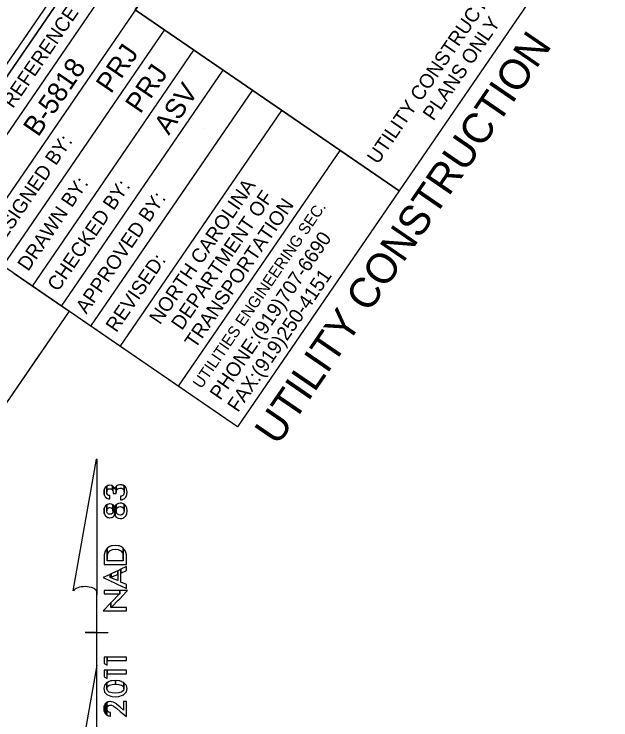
# Model space of a CAD drawing. Extents: x 1439200 to 1641636, y 393269 to 606444.
# Drawn here: x 1641246 to 1641330.1, y 393923.4 to 394022.9 of the extents above; entities that cross this region are included whole.
import ezdxf

# ---------------------------------------------------------------- set-up
doc = ezdxf.new("R2010")
doc.units = 0
for name, color, linetype in [('North Arrow NAD83 CELL', 7, 'Continuous'), ('Sheet Data Field CELL', 7, 'Continuous'), ('Sheet Plot Border Inside CELL', 7, 'Continuous'), ('Sheet Sticker Exception Certification CELL', 7, 'Continuous'), ('UC Plan Sheet 34 CELL', 7, 'Continuous')]:
    doc.layers.add(name, color=color, linetype=linetype)

msp = doc.modelspace()

# ---------------------------------------------------------------- linework, layer by layer
at = {"layer": 'North Arrow NAD83 CELL'}
for p, q in [((1641275.714, 393965.954), (1641254.905, 393980.224)), ((1641251.013, 393977.029), (1641216.651, 393926.919)), ((1641249.54, 393974.88), (1641224.439, 393938.276)), ((1641254.348, 393941.624), (1641257.636, 393960.163)), ((1641257.656, 393960.163), (1641257.636, 393960.163)), ((1641257.656, 393960.163), (1641257.636, 393960.163)), ((1641257.656, 393960.163), (1641257.648, 393941.043)), ((1641257.644, 393931.123), (1641257.648, 393941.603)), ((1641257.648, 393941.043), (1641257.648, 393941.583)), ((1641256.046, 393935.764), (1641256.026, 393935.764)), ((1641257.466, 393935.763), (1641256.046, 393935.764)), ((1641256.066, 393935.764), (1641259.266, 393935.762)), ((1641257.644, 393931.123), (1641254.296, 393912.224)), ((1641257.656, 393912.303), (1641257.644, 393931.123))]:
    msp.add_line(p, q, dxfattribs=at)
for points in [[(1641259.444, 393954.569), (1641259.483, 393954.565), (1641259.483, 393955.036), (1641259.444, 393955.038), (1641259.329, 393955.065), (1641259.313, 393955.07), (1641259.311, 393955.07), (1641259.175, 393955.166), (1641259.168, 393955.177), (1641259.158, 393955.195), (1641259.091, 393955.313), (1641259.077, 393955.397), (1641259.072, 393955.42), (1641259.057, 393955.51), (1641259.057, 393956.376), (1641258.884, 393956.258), (1641258.836, 393956.176), (1641258.836, 393956.175), (1641258.697, 393955.935), (1641258.684, 393955.843), (1641258.684, 393955.182), (1641258.698, 393955.155), (1641258.837, 393954.872), (1641258.884, 393954.832), (1641259.057, 393954.686), (1641259.073, 393954.673), (1641259.077, 393954.672), (1641259.091, 393954.666), (1641259.158, 393954.642), (1641259.169, 393954.638), (1641259.175, 393954.636), (1641259.311, 393954.587), (1641259.313, 393954.586), (1641259.329, 393954.581)], [(1641259.804, 393955.9), (1641259.859, 393955.859), (1641259.859, 393956.406), (1641259.804, 393956.442), (1641259.699, 393956.461), (1641259.502, 393956.498), (1641259.487, 393956.501), (1641259.482, 393956.5), (1641259.443, 393956.494), (1641259.329, 393956.474), (1641259.312, 393956.471), (1641259.31, 393956.471), (1641259.31, 393956.471), (1641259.174, 393956.448), (1641259.168, 393956.447), (1641259.158, 393956.445), (1641259.091, 393956.4), (1641259.076, 393956.389), (1641259.072, 393956.387), (1641259.057, 393956.376), (1641259.057, 393955.51), (1641259.072, 393955.661), (1641259.076, 393955.702), (1641259.091, 393955.728), (1641259.158, 393955.853), (1641259.168, 393955.873), (1641259.174, 393955.877), (1641259.31, 393955.974), (1641259.312, 393955.976), (1641259.329, 393955.979), (1641259.443, 393956.001), (1641259.482, 393956.008), (1641259.487, 393956.009), (1641259.502, 393956.012), (1641259.7, 393955.977)], [(1641259.859, 393955.858), (1641259.941, 393955.693), (1641259.941, 393956.355), (1641259.859, 393956.406)], [(1641260.255, 393955.353), (1641260.382, 393955.353), (1641260.382, 393956.324), (1641260.255, 393956.155), (1641260.195, 393955.95), (1641260.155, 393956.101), (1641260.035, 393956.295), (1641259.965, 393956.339), (1641259.964, 393956.34), (1641259.941, 393956.355), (1641259.941, 393955.692), (1641259.965, 393955.5), (1641259.966, 393955.353), (1641260.036, 393955.353), (1641260.155, 393955.353), (1641260.195, 393955.353)], [(1641261.479, 393955.716), (1641261.514, 393955.544), (1641261.514, 393956.405), (1641261.479, 393956.427), (1641261.464, 393956.437), (1641261.464, 393956.437), (1641261.354, 393956.509), (1641261.337, 393956.512), (1641261.33, 393956.513), (1641261.253, 393956.528), (1641261.149, 393956.547), (1641261.138, 393956.549), (1641261.018, 393956.571), (1641260.921, 393956.558), (1641260.719, 393956.53), (1641260.693, 393956.527), (1641260.55, 393956.451), (1641260.435, 393956.39), (1641260.429, 393956.387), (1641260.388, 393956.332), (1641260.382, 393956.324), (1641260.382, 393955.455), (1641260.388, 393955.607), (1641260.429, 393955.775), (1641260.435, 393955.8), (1641260.551, 393955.959), (1641260.693, 393956.043), (1641260.72, 393956.059), (1641260.922, 393956.094), (1641261.018, 393956.084), (1641261.138, 393956.072), (1641261.149, 393956.066), (1641261.253, 393956.014), (1641261.331, 393955.975), (1641261.337, 393955.966), (1641261.354, 393955.941), (1641261.465, 393955.788)], [(1641261.905, 393955.153), (1641261.939, 393955.555), (1641261.905, 393955.74), (1641261.86, 393955.981), (1641261.749, 393956.164), (1641261.661, 393956.308), (1641261.519, 393956.401), (1641261.514, 393956.405), (1641261.514, 393955.544), (1641261.479, 393955.251), (1641261.465, 393955.23), (1641261.355, 393955.068), (1641261.337, 393955.042), (1641261.331, 393955.038), (1641261.254, 393954.998), (1641261.15, 393954.943), (1641261.138, 393954.942), (1641261.019, 393954.934), (1641261.008, 393954.934), (1641261.008, 393954.437), (1641261.019, 393954.439), (1641261.139, 393954.456), (1641261.15, 393954.457), (1641261.254, 393954.472), (1641261.331, 393954.504), (1641261.337, 393954.507), (1641261.355, 393954.515), (1641261.465, 393954.56), (1641261.48, 393954.567), (1641261.515, 393954.581), (1641261.52, 393954.584), (1641261.662, 393954.73), (1641261.749, 393954.82), (1641261.861, 393955.058)], [(1641258.642, 393955.552), (1641258.684, 393955.182), (1641258.684, 393955.843)], [(1641258.693, 393952.537), (1641258.699, 393952.501), (1641258.698, 393953.277), (1641258.693, 393953.268), (1641258.643, 393952.886), (1641258.643, 393952.885)], [(1641260.093, 393952.207), (1641260.176, 393952.361), (1641260.176, 393953.414), (1641260.092, 393953.578), (1641260.088, 393953.582), (1641259.962, 393953.72), (1641259.96, 393953.723), (1641259.931, 393953.738), (1641259.932, 393952.883), (1641259.905, 393952.685), (1641259.814, 393952.532), (1641259.747, 393952.487), (1641259.747, 393952.487), (1641259.744, 393952.485), (1641259.674, 393952.439), (1641259.502, 393952.407), (1641259.44, 393952.418), (1641259.321, 393952.439), (1641259.173, 393952.549), (1641259.17, 393952.552), (1641259.124, 393952.636), (1641259.087, 393952.703), (1641259.062, 393952.891), (1641259.062, 393953.738), (1641258.869, 393953.592), (1641258.698, 393953.277), (1641258.699, 393952.501), (1641258.87, 393952.177), (1641259.063, 393952.032), (1641259.087, 393952.013), (1641259.124, 393951.985), (1641259.171, 393951.973), (1641259.173, 393951.972), (1641259.321, 393951.934), (1641259.441, 393951.903), (1641259.503, 393951.91), (1641259.675, 393951.93), (1641259.745, 393951.939), (1641259.748, 393951.941), (1641259.815, 393951.974), (1641259.905, 393952.02), (1641259.932, 393952.034), (1641259.961, 393952.048), (1641259.963, 393952.05), (1641260.089, 393952.2)], [(1641259.905, 393953.089), (1641259.932, 393952.883), (1641259.931, 393953.738), (1641259.905, 393953.753), (1641259.814, 393953.801), (1641259.747, 393953.838), (1641259.744, 393953.838), (1641259.674, 393953.845), (1641259.502, 393953.863), (1641259.502, 393953.862), (1641259.44, 393953.869), (1641259.32, 393953.837), (1641259.172, 393953.798), (1641259.17, 393953.797), (1641259.124, 393953.785), (1641259.087, 393953.757), (1641259.062, 393953.738), (1641259.062, 393952.891), (1641259.087, 393953.069), (1641259.124, 393953.14), (1641259.17, 393953.229), (1641259.172, 393953.23), (1641259.321, 393953.335), (1641259.44, 393953.356), (1641259.502, 393953.367), (1641259.674, 393953.335), (1641259.744, 393953.288), (1641259.747, 393953.286), (1641259.814, 393953.242)], [(1641260.245, 393952.202), (1641260.25, 393952.191), (1641260.25, 393953.579), (1641260.245, 393953.573), (1641260.176, 393953.414), (1641260.176, 393952.36)], [(1641261.894, 393952.49), (1641261.94, 393952.887), (1641261.893, 393953.291), (1641261.892, 393953.293), (1641261.728, 393953.646), (1641261.726, 393953.648), (1641261.519, 393953.813), (1641261.519, 393952.886), (1641261.487, 393952.638), (1641261.432, 393952.548), (1641261.432, 393952.547), (1641261.371, 393952.447), (1641261.19, 393952.332), (1641261.077, 393952.311), (1641261.074, 393952.31), (1641260.97, 393952.291), (1641260.738, 393952.332), (1641260.713, 393952.35), (1641260.547, 393952.468), (1641260.546, 393952.47), (1641260.438, 393952.664), (1641260.425, 393952.762), (1641260.418, 393952.819), (1641260.41, 393952.885), (1641260.409, 393953.769), (1641260.25, 393953.58), (1641260.25, 393952.19), (1641260.41, 393952.001), (1641260.418, 393951.991), (1641260.426, 393951.983), (1641260.438, 393951.976), (1641260.546, 393951.921), (1641260.547, 393951.921), (1641260.713, 393951.838), (1641260.738, 393951.835), (1641260.97, 393951.807), (1641261.074, 393951.794), (1641261.077, 393951.794), (1641261.19, 393951.824), (1641261.371, 393951.873), (1641261.432, 393951.889), (1641261.487, 393951.933), (1641261.52, 393951.96), (1641261.727, 393952.127), (1641261.729, 393952.131), (1641261.893, 393952.481)], [(1641261.486, 393953.134), (1641261.519, 393952.886), (1641261.519, 393953.813), (1641261.486, 393953.839), (1641261.431, 393953.883), (1641261.371, 393953.899), (1641261.189, 393953.947), (1641261.076, 393953.977), (1641261.073, 393953.978), (1641260.969, 393953.966), (1641260.969, 393953.965), (1641260.737, 393953.939), (1641260.712, 393953.936), (1641260.546, 393953.848), (1641260.545, 393953.847), (1641260.437, 393953.79), (1641260.425, 393953.783), (1641260.418, 393953.78), (1641260.409, 393953.77), (1641260.41, 393952.885), (1641260.418, 393952.951), (1641260.425, 393953.009), (1641260.438, 393953.108), (1641260.546, 393953.306), (1641260.547, 393953.306), (1641260.712, 393953.424), (1641260.737, 393953.442), (1641260.969, 393953.481), (1641261.073, 393953.463), (1641261.076, 393953.462), (1641261.19, 393953.442), (1641261.371, 393953.325), (1641261.432, 393953.224)], [(1641261.848, 393945.328), (1641261.861, 393945.328), (1641261.86, 393946.025), (1641261.848, 393946.687), (1641261.708, 393947.229), (1641261.393, 393947.636), (1641261.394, 393945.843), (1641261.383, 393945.843), (1641261.365, 393945.843), (1641261.285, 393945.842), (1641261.042, 393945.842), (1641260.857, 393945.842), (1641260.683, 393945.842), (1641260.271, 393945.842), (1641260.268, 393945.842), (1641259.853, 393945.842), (1641259.684, 393945.842), (1641259.494, 393945.842), (1641259.251, 393945.842), (1641259.176, 393945.842), (1641259.153, 393945.842), (1641259.14, 393945.842), (1641259.14, 393947.626), (1641258.832, 393947.228), (1641258.693, 393946.685), (1641258.677, 393946.024), (1641258.677, 393945.326), (1641258.693, 393945.326), (1641258.832, 393945.326), (1641259.141, 393945.326), (1641259.153, 393945.326), (1641259.177, 393945.326), (1641259.251, 393945.326), (1641259.494, 393945.327), (1641259.685, 393945.327), (1641259.853, 393945.327), (1641260.269, 393945.327), (1641260.271, 393945.327), (1641260.683, 393945.327), (1641260.857, 393945.327), (1641261.042, 393945.327), (1641261.286, 393945.327), (1641261.365, 393945.327), (1641261.384, 393945.327), (1641261.394, 393945.327), (1641261.709, 393945.328)], [(1641261.364, 393946.693), (1641261.383, 393946.627), (1641261.383, 393947.649), (1641261.364, 393947.673), (1641261.285, 393947.716), (1641261.041, 393947.846), (1641260.856, 393947.945), (1641260.682, 393947.969), (1641260.682, 393947.969), (1641260.27, 393948.026), (1641260.268, 393948.026), (1641259.852, 393947.968), (1641259.683, 393947.945), (1641259.493, 393947.842), (1641259.25, 393947.712), (1641259.176, 393947.672), (1641259.152, 393947.642), (1641259.14, 393947.626), (1641259.14, 393946.03), (1641259.152, 393946.626), (1641259.176, 393946.71), (1641259.25, 393946.976), (1641259.493, 393947.263), (1641259.684, 393947.356), (1641259.853, 393947.439), (1641260.268, 393947.491), (1641260.27, 393947.49), (1641260.682, 393947.439), (1641260.856, 393947.354), (1641261.042, 393947.263), (1641261.285, 393946.977)], [(1641261.383, 393946.626), (1641261.394, 393946.031), (1641261.393, 393947.636), (1641261.383, 393947.649)], [(1641261.042, 393942.33), (1641261.862, 393941.948), (1641261.862, 393942.492), (1641261.041, 393942.86), (1641261.041, 393944.646), (1641260.609, 393944.445), (1641260.61, 393943.052), (1641259.885, 393943.377), (1641259.883, 393943.378), (1641259.702, 393943.444), (1641259.697, 393943.445), (1641259.523, 393943.494), (1641259.522, 393943.938), (1641258.554, 393943.487), (1641259.523, 393943.036), (1641259.697, 393942.955), (1641259.702, 393942.953), (1641259.883, 393942.868), (1641259.885, 393942.867), (1641260.61, 393942.53)], [(1641259.885, 393943.615), (1641260.609, 393943.936), (1641260.609, 393944.445), (1641259.885, 393944.107), (1641259.883, 393944.106), (1641259.702, 393944.022), (1641259.696, 393944.02), (1641259.697, 393943.545), (1641259.702, 393943.547), (1641259.883, 393943.614)], [(1641261.041, 393944.12), (1641261.861, 393944.483), (1641261.861, 393945.029), (1641261.041, 393944.646)], [(1641259.523, 393943.493), (1641259.697, 393943.545), (1641259.696, 393944.019), (1641259.522, 393943.938)], [(1641260.678, 393941.173), (1641260.886, 393941.173), (1641260.885, 393941.648), (1641260.678, 393941.648), (1641260.501, 393941.648), (1641260.004, 393941.648), (1641259.814, 393941.647), (1641258.678, 393941.647), (1641258.679, 393941.172), (1641259.814, 393941.173), (1641260.005, 393941.173), (1641260.501, 393941.173)], [(1641261.863, 393941.521), (1641261.986, 393941.648), (1641261.863, 393941.648), (1641260.885, 393941.648), (1641260.886, 393941.173), (1641260.679, 393940.998), (1641260.501, 393940.825), (1641260.005, 393940.309), (1641259.814, 393940.111), (1641259.653, 393939.943), (1641259.653, 393939.279), (1641259.815, 393939.406), (1641260.005, 393939.586), (1641260.502, 393940.103), (1641260.679, 393940.287), (1641260.886, 393940.503)], [(1641260.887, 393938.805), (1641261.864, 393938.806), (1641261.864, 393939.28), (1641260.886, 393939.279), (1641260.679, 393939.279), (1641260.502, 393939.279), (1641260.005, 393939.279), (1641259.815, 393939.279), (1641259.653, 393939.279), (1641259.653, 393939.943), (1641258.556, 393938.804), (1641259.653, 393938.805), (1641259.815, 393938.805), (1641260.006, 393938.805), (1641260.502, 393938.805), (1641260.679, 393938.805)], [(1641258.694, 393931.361), (1641259.107, 393931.159), (1641259.106, 393932.289), (1641258.693, 393932.289)], [(1641259.107, 393931.815), (1641261.846, 393931.816), (1641261.846, 393932.29), (1641259.106, 393932.289)], [(1641258.694, 393929.486), (1641259.108, 393929.284), (1641259.107, 393930.414), (1641258.694, 393930.414)], [(1641259.107, 393929.94), (1641261.847, 393929.941), (1641261.847, 393930.415), (1641259.107, 393930.414)], [(1641261.838, 393927.38), (1641261.93, 393927.832), (1641261.837, 393928.273), (1641261.832, 393928.298), (1641261.488, 393928.673), (1641261.488, 393927.825), (1641261.482, 393927.803), (1641261.479, 393927.792), (1641261.412, 393927.555), (1641261.156, 393927.357), (1641261.154, 393927.357), (1641261.154, 393927.356), (1641260.925, 393927.294), (1641260.921, 393927.293), (1641260.756, 393927.247), (1641260.746, 393927.245), (1641260.287, 393927.204), (1641260.282, 393927.204), (1641260.277, 393927.205), (1641259.819, 393927.244), (1641259.645, 393927.291), (1641259.64, 393927.292), (1641259.418, 393927.352), (1641259.41, 393927.354), (1641259.152, 393927.554), (1641259.085, 393927.81), (1641259.082, 393927.818), (1641259.076, 393927.841), (1641259.076, 393928.68), (1641258.737, 393928.31), (1641258.733, 393928.291), (1641258.633, 393927.836), (1641258.633, 393927.836), (1641258.733, 393927.364), (1641258.738, 393927.36), (1641259.077, 393926.994), (1641259.083, 393926.987), (1641259.085, 393926.985), (1641259.152, 393926.957), (1641259.411, 393926.851), (1641259.418, 393926.848), (1641259.64, 393926.757), (1641259.645, 393926.756), (1641259.82, 393926.738), (1641260.277, 393926.69), (1641260.282, 393926.689), (1641260.287, 393926.69), (1641260.746, 393926.736), (1641260.756, 393926.737), (1641260.921, 393926.754), (1641260.925, 393926.754), (1641261.154, 393926.848), (1641261.156, 393926.849), (1641261.412, 393926.953), (1641261.479, 393926.981), (1641261.482, 393926.982), (1641261.489, 393926.989), (1641261.833, 393927.374)], [(1641259.819, 393928.424), (1641260.276, 393928.461), (1641260.276, 393928.976), (1641259.819, 393928.931), (1641259.645, 393928.914), (1641259.639, 393928.912), (1641259.639, 393928.912), (1641259.417, 393928.822), (1641259.417, 393928.822), (1641259.41, 393928.819), (1641259.151, 393928.715), (1641259.151, 393928.715), (1641259.084, 393928.688), (1641259.082, 393928.687), (1641259.076, 393928.68), (1641259.076, 393927.841), (1641259.082, 393927.864), (1641259.085, 393927.871), (1641259.151, 393928.112), (1641259.41, 393928.311), (1641259.417, 393928.317), (1641259.64, 393928.376), (1641259.645, 393928.377)], [(1641261.482, 393927.848), (1641261.488, 393927.825), (1641261.488, 393928.673), (1641261.482, 393928.68), (1641261.479, 393928.683), (1641261.412, 393928.71), (1641261.155, 393928.816), (1641261.153, 393928.817), (1641260.924, 393928.912), (1641260.92, 393928.914), (1641260.755, 393928.93), (1641260.745, 393928.931), (1641260.286, 393928.976), (1641260.281, 393928.976), (1641260.276, 393928.976), (1641260.276, 393928.461), (1641260.281, 393928.461), (1641260.287, 393928.46), (1641260.745, 393928.424), (1641260.755, 393928.423), (1641260.92, 393928.378), (1641260.924, 393928.377), (1641261.153, 393928.316), (1641261.155, 393928.314), (1641261.412, 393928.113), (1641261.479, 393927.86)], [(1641258.823, 393924.343), (1641258.828, 393924.333), (1641258.828, 393925.693), (1641258.823, 393925.689), (1641258.688, 393925.39), (1641258.671, 393925.354), (1641258.634, 393924.982), (1641258.634, 393924.982), (1641258.672, 393924.735), (1641258.688, 393924.626)], [(1641258.828, 393924.333), (1641259.063, 393924.112), (1641259.063, 393925.897), (1641258.828, 393925.693)], [(1641259.517, 393923.974), (1641259.573, 393923.97), (1641259.573, 393924.467), (1641259.517, 393924.472), (1641259.492, 393924.475), (1641259.486, 393924.477), (1641259.348, 393924.527), (1641259.334, 393924.537), (1641259.309, 393924.556), (1641259.194, 393924.645), (1641259.163, 393924.707), (1641259.104, 393924.825), (1641259.098, 393924.838), (1641259.089, 393925.084), (1641259.088, 393925.919), (1641259.063, 393925.897), (1641259.063, 393924.111), (1641259.089, 393924.1), (1641259.098, 393924.096), (1641259.105, 393924.093), (1641259.163, 393924.067), (1641259.194, 393924.054), (1641259.31, 393924.002), (1641259.334, 393923.991), (1641259.348, 393923.99), (1641259.486, 393923.977), (1641259.492, 393923.977)], [(1641261.437, 393924.237), (1641261.849, 393923.893), (1641261.849, 393926.024), (1641261.436, 393926.024), (1641261.437, 393924.813), (1641260.969, 393925.22), (1641260.424, 393925.665), (1641260.419, 393925.67), (1641259.993, 393925.922), (1641259.993, 393925.921), (1641259.982, 393925.929), (1641259.711, 393925.982), (1641259.573, 393926.01), (1641259.516, 393926.021), (1641259.491, 393926.015), (1641259.485, 393926.014), (1641259.347, 393925.985), (1641259.334, 393925.982), (1641259.309, 393925.977), (1641259.193, 393925.952), (1641259.193, 393925.952), (1641259.163, 393925.946), (1641259.104, 393925.933), (1641259.098, 393925.928), (1641259.088, 393925.92), (1641259.089, 393925.084), (1641259.098, 393925.111), (1641259.104, 393925.129), (1641259.163, 393925.298), (1641259.194, 393925.328), (1641259.309, 393925.441), (1641259.334, 393925.449), (1641259.347, 393925.454), (1641259.485, 393925.501), (1641259.491, 393925.5), (1641259.516, 393925.5), (1641259.573, 393925.499), (1641259.711, 393925.497), (1641259.982, 393925.39), (1641259.993, 393925.386), (1641260.419, 393925.085), (1641260.424, 393925.082), (1641260.969, 393924.627)]]:
    msp.add_lwpolyline(points, close=True, dxfattribs=at)
msp.add_ellipse((1641256.003, 393941.425), major_axis=(1.692, -0.013), ratio=0.461098, start_param=0.216388, end_param=2.908219, dxfattribs=at)
at = {"layer": 'Sheet Plot Border Inside CELL'}
msp.add_lwpolyline([(1641279.537, 394066.32), (1640902.543, 393516.564), (1641250.606, 393277.881), (1641627.6, 393827.636)], close=True, dxfattribs=at)
at = {"layer": 'Sheet Sticker Exception Certification CELL'}
for p, q in [((1641246, 393986.33), (1641253.752, 393981.014)), ((1641253.748, 393981.017), (1641208.496, 393915.027))]:
    msp.add_line(p, q, dxfattribs=at)
at = {"layer": 'UC Plan Sheet 34 CELL'}
for p, q in [((1641236.169, 393993.072), (1641281.377, 394058.996)), ((1641244.437, 393987.402), (1641267.226, 394020.634)), ((1641248.569, 393984.569), (1641271.358, 394017.8)), ((1641252.701, 393981.735), (1641275.49, 394014.967)), ((1641260.487, 394015.245), (1641260.487, 394015.245)), ((1641252.445, 394012.385), (1641252.445, 394012.385)), ((1641256.833, 393978.902), (1641279.621, 394012.134)), ((1641264.623, 394012.409), (1641264.623, 394012.409)), ((1641260.969, 393976.066), (1641283.757, 394009.297)), ((1641268.755, 394009.576), (1641268.755, 394009.576)), ((1641272.887, 394006.742), (1641272.887, 394006.742)), ((1641269.166, 393970.444), (1641291.955, 394003.676))]:
    msp.add_line(p, q, dxfattribs=at)
msp.add_lwpolyline([(1641277.55, 394061.62), (1640938.222, 393566.79), (1641284.603, 393329.26), (1641623.931, 393824.09)], close=True, dxfattribs=at)
for points in [[(1641232.343, 393995.695), (1641277.55, 394061.62), (1641285.492, 394056.174)], [(1641285.492, 394056.174), (1641240.285, 393990.249), (1641232.343, 393995.695)], [(1641322.707, 394030.653), (1641300.289, 393997.961), (1641263.09, 394023.47), (1641285.509, 394056.162)], [(1641263.073, 394023.481), (1641300.289, 393997.961), (1641277.5, 393964.729), (1641232.343, 393995.695)]]:
    msp.add_lwpolyline(points, dxfattribs=at)

# ---------------------------------------------------------------- texts
at = {"layer": 'Sheet Data Field CELL'}
for s, p in [('PRJ', (1641259.658, 394011.56)), ('B-5818', (1641249.396, 394005.464)), ('PRJ', (1641263.794, 394008.724)), ('ASV', (1641267.81, 394005.722))]:
    msp.add_text(s, height=2.8, rotation=55.55969, dxfattribs=at).set_placement(p)
at = {"layer": 'UC Plan Sheet 34 CELL'}
for s, height, p in [('UTILITY CONSTRUCTION', 2.00457, (1641297.277, 394001.615)), ('PROJECT REFERENCE NO.', 2.00457, (1641238.334, 393998.571)), ('PLANS ONLY', 2.0046, (1641305.12, 394007.738)), ('UTILITY CONSTRUCTION', 4.25, (1641283.163, 393961.933)), ('DESIGNED BY:', 2.00457, (1641243.531, 393989.272)), ('DRAWN BY:', 2.0046, (1641247.975, 393986.54)), ('CHECKED BY:', 2.00457, (1641252.184, 393983.678)), ('NORTH CAROLINA', 2.00457, (1641266.564, 393979.018)), ('DEPARTMENT OF', 2.00457, (1641269.656, 393978.214)), ('APPROVED BY:', 2.00457, (1641256.191, 393980.512)), ('TRANSPORTATION', 2.00457, (1641271.548, 393975.65)), ('UTILITIES ENGINEERING SEC.', 1.60366, (1641272.395, 393970.004)), ('PHONE:(919)707-6690', 2.00457, (1641275.085, 393968.357)), ('REVISED:', 2.0046, (1641260.412, 393977.915)), ('FAX:(919)250-4151', 2.00457, (1641277.563, 393966.658))]:
    msp.add_text(s, height=height, rotation=55.55969, dxfattribs=at).set_placement(p)

doc.saveas('drawing.dxf')
